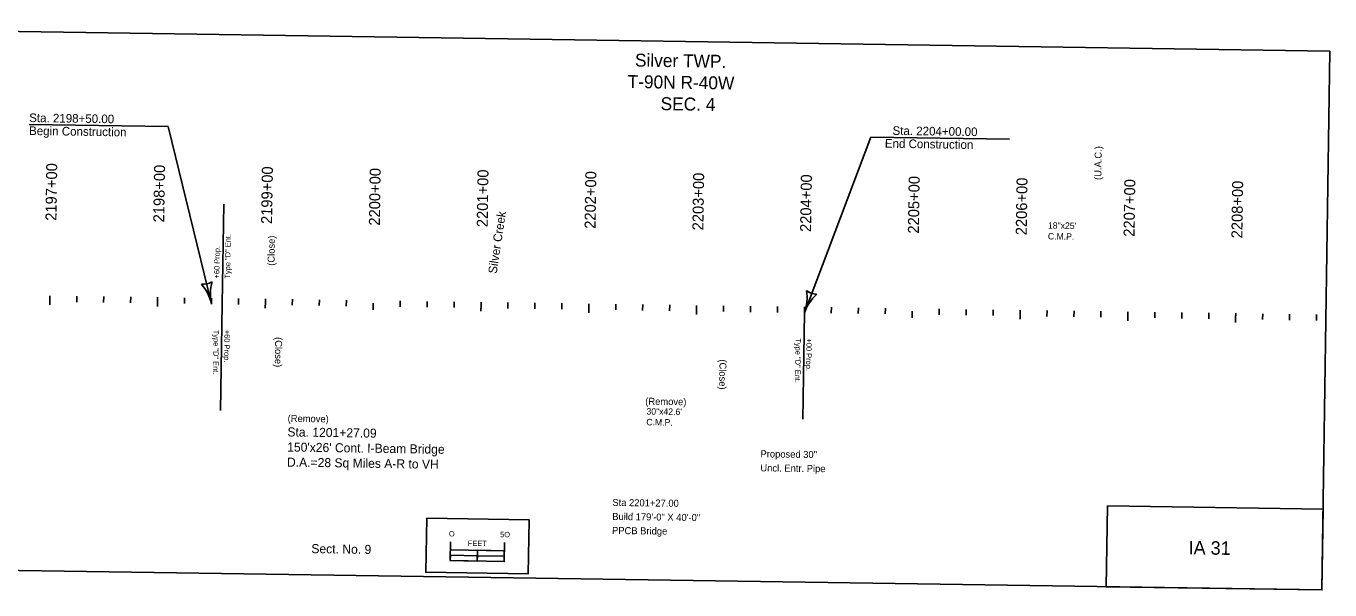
# Model space of a CAD drawing. Extents: x 14295116 to 14303545, y 8637313 to 8653417.
# Drawn here: x 14300189 to 14301398, y 8637313 to 8637836 of the extents above; entities that cross this region are included whole.
import ezdxf

# ---------------------------------------------------------------- set-up
doc = ezdxf.new("R2010")
doc.units = 0
for name, color, linetype in [('_CIVIL_CONSTRUCTION', 7, 'Continuous'), ('Draft_DNC', 7, 'Continuous'), ('dsnCellsNorthArrow', 7, 'Continuous'), ('dsnCellsScaleBlock', 7, 'Continuous'), ('dsnProfileBarGraphArrows', 7, 'Continuous'), ('dsnProfileDitchGradePropLeft', 7, 'Continuous'), ('dsnProfileGradeExistLine', 7, 'Continuous'), ('dsnTextFinalPlan', 7, 'Continuous'), ('dsnTextNote', 7, 'Continuous'), ('dsnTextProfileBarGraphRight', 7, 'Continuous'), ('dsnTextProfileDitchPropLeft', 7, 'Continuous'), ('G Prop 6 Valve (B1) CELL', 7, 'Continuous')]:
    doc.layers.add(name, color=color, linetype=linetype)

msp = doc.modelspace()

# ---------------------------------------------------------------- linework, layer by layer
at = {"layer": '_CIVIL_CONSTRUCTION'}
for p, q in [((14299830.8, 8637836.3), (14301398.1, 8637813)), ((14301390.7, 8637313), (14301398.1, 8637813)), ((14299823.4, 8637336.3), (14301390.7, 8637313))]:
    msp.add_line(p, q, dxfattribs=at)
at = {"layer": 'Draft_DNC'}
for p, q in [((14300210.9, 8637583.6), (14300210.8, 8637577.5)), ((14300235.8, 8637580.2), (14300235.9, 8637585.7)), ((14300260.8, 8637579.8), (14300260.9, 8637585.3)), ((14300285.8, 8637579.5), (14300285.9, 8637584.9)), ((14300310.8, 8637582.2), (14300310.8, 8637576)), ((14300335.8, 8637578.7), (14300335.9, 8637584.2)), ((14300360.8, 8637578.4), (14300360.9, 8637583.8)), ((14300385.8, 8637578), (14300385.9, 8637583.4)), ((14300410.8, 8637580.7), (14300410.7, 8637574.6)), ((14300435.8, 8637577.2), (14300435.9, 8637582.7)), ((14300460.8, 8637576.9), (14300460.9, 8637582.3)), ((14300485.8, 8637576.5), (14300485.9, 8637582)), ((14300510.8, 8637579.2), (14300510.7, 8637573.1)), ((14300535.8, 8637575.8), (14300535.9, 8637581.2)), ((14300560.8, 8637575.4), (14300560.9, 8637580.8)), ((14300585.8, 8637575), (14300585.8, 8637580.5)), ((14300610.8, 8637577.7), (14300610.7, 8637571.6)), ((14300635.8, 8637574.3), (14300635.8, 8637579.7)), ((14300660.8, 8637573.9), (14300660.8, 8637579.4)), ((14300685.8, 8637573.5), (14300685.8, 8637579)), ((14300710.8, 8637576.2), (14300710.7, 8637570.1)), ((14300735.8, 8637572.8), (14300735.8, 8637578.3)), ((14300760.7, 8637572.4), (14300760.8, 8637577.9)), ((14300785.7, 8637572), (14300785.8, 8637577.5)), ((14300810.8, 8637574.7), (14300810.7, 8637568.6)), ((14300835.7, 8637571.3), (14300835.8, 8637576.8)), ((14300860.7, 8637570.9), (14300860.8, 8637576.4)), ((14300885.7, 8637570.6), (14300885.8, 8637576)), ((14300935.7, 8637569.8), (14300935.8, 8637575.3)), ((14300960.7, 8637569.5), (14300960.8, 8637574.9)), ((14300985.7, 8637569.1), (14300985.8, 8637574.5)), ((14300910.8, 8637573.3), (14300910.7, 8637567.1)), ((14301010.8, 8637571.8), (14301010.7, 8637565.6)), ((14301035.7, 8637568.3), (14301035.8, 8637573.8)), ((14301060.7, 8637568), (14301060.8, 8637573.4)), ((14301085.7, 8637567.6), (14301085.8, 8637573.1)), ((14301110.8, 8637570.3), (14301110.7, 8637564.2)), ((14301135.7, 8637566.9), (14301135.8, 8637572.3)), ((14301160.7, 8637566.5), (14301160.8, 8637571.9)), ((14301185.7, 8637566.1), (14301185.8, 8637571.6)), ((14301210.7, 8637568.8), (14301210.7, 8637562.7)), ((14301235.7, 8637565.4), (14301235.8, 8637570.8)), ((14301260.7, 8637565), (14301260.8, 8637570.5)), ((14301285.7, 8637564.6), (14301285.8, 8637570.1)), ((14301310.7, 8637567.3), (14301310.6, 8637561.2)), ((14301335.7, 8637563.9), (14301335.8, 8637569.3)), ((14301360.7, 8637563.5), (14301360.8, 8637569)), ((14301385.7, 8637563.1), (14301385.8, 8637568.6))]:
    msp.add_line(p, q, dxfattribs=at)
at = {"layer": 'dsnCellsNorthArrow'}
for p, q in [((14300191.8, 8637744.9), (14300320.7, 8637743)), ((14300360.8, 8637578.4), (14300320.7, 8637743)), ((14300910.7, 8637570.2), (14300972.2, 8637733.3)), ((14301101.1, 8637731.4), (14300972.2, 8637733.3))]:
    msp.add_line(p, q, dxfattribs=at)
for centre, radius, start, end in [((14300353, 8637613.1), 16.4, 264.823, 300.2897), ((14300402.3, 8637587.6), 42.5, 164.4839, 192.5564), ((14300319.3, 8637569.1), 42.5, 12.5564, 40.6289), ((14300870.7, 8637584.4), 42.5, 340.4638, 8.5362), ((14300950.8, 8637556), 42.5, 132.3913, 160.4638), ((14300922.6, 8637603.8), 16.4, 232.7304, 268.1971)]:
    msp.add_arc(centre, radius, start, end, dxfattribs=at)
at = {"layer": 'dsnCellsScaleBlock'}
msp.add_line((14300607.3, 8637339.8), (14300607.4, 8637349.8), dxfattribs=at)
msp.add_line((14300607.3, 8637339.8), (14300607.4, 8637349.8), dxfattribs=at)
for points in [[(14300559.6, 8637329.5), (14300560.4, 8637379.5), (14300655.4, 8637378.1), (14300654.6, 8637328.1)], [(14300582.3, 8637340.2), (14300607.3, 8637339.8), (14300607.4, 8637344.8), (14300582.4, 8637345.2)], [(14300607.4, 8637344.8), (14300632.4, 8637344.5), (14300632.4, 8637349.4), (14300607.4, 8637349.8)]]:
    msp.add_lwpolyline(points, close=True, dxfattribs=at)
for points in [[(14300582.5, 8637357.7), (14300582.3, 8637340.2), (14300632.3, 8637339.4), (14300632.5, 8637356.9)], [(14300582.4, 8637350.2), (14300632.4, 8637349.4)]]:
    msp.add_lwpolyline(points, dxfattribs=at)
at = {"layer": 'dsnProfileDitchGradePropLeft'}
for p, q in [((14300370.8, 8637578.2), (14300372.2, 8637670.9)), ((14300370.8, 8637578.2), (14300369.3, 8637479.6)), ((14300910.7, 8637570.2), (14300909.3, 8637471.6))]:
    msp.add_line(p, q, dxfattribs=at)
at = {"layer": 'dsnTextFinalPlan'}
msp.add_lwpolyline([(14300560.4, 8637379.5), (14300655.4, 8637378.1), (14300654.6, 8637328.1), (14300559.6, 8637329.5)], close=True, dxfattribs=at)
msp.add_lwpolyline([(14300560.4, 8637379.5), (14300655.4, 8637378.1), (14300654.6, 8637328.1), (14300559.6, 8637329.5)], close=True, dxfattribs=at)
at = {"layer": 'dsnTextProfileDitchPropLeft'}
for points in [[(14301191.9, 8637391), (14301391.8, 8637388), (14301390.7, 8637313), (14301190.7, 8637316)], [(14301390.7, 8637313), (14301190.7, 8637316), (14301191.9, 8637391), (14301391.8, 8637388)]]:
    msp.add_lwpolyline(points, close=True, dxfattribs=at)
at = {"layer": 'G Prop 6 Valve (B1) CELL'}
for p, q in [((14300210.8, 8637580.6), (14300210.9, 8637586)), ((14300310.8, 8637579.1), (14300310.9, 8637584.6)), ((14300410.8, 8637577.6), (14300410.9, 8637583.1)), ((14300510.8, 8637579.2), (14300510.7, 8637573.1)), ((14300610.8, 8637574.6), (14300610.8, 8637580.1)), ((14300710.8, 8637573.2), (14300710.8, 8637578.6)), ((14300810.7, 8637571.7), (14300810.8, 8637577.1)), ((14300910.7, 8637570.2), (14300910.8, 8637575.7)), ((14301010.8, 8637571.8), (14301010.7, 8637565.6)), ((14301110.7, 8637567.2), (14301110.8, 8637572.7)), ((14301210.7, 8637565.7), (14301210.8, 8637571.2)), ((14301310.7, 8637564.3), (14301310.8, 8637569.7))]:
    msp.add_line(p, q, dxfattribs=at)

# ---------------------------------------------------------------- texts
at = {"layer": 'Draft_DNC'}
for s, p in [('2197+00', (14300217, 8637655.5)), ('2198+00', (14300317, 8637654)), ('2199+00', (14300417, 8637652.5)), ('2200+00', (14300517, 8637651)), ('2201+00', (14300617, 8637649.6)), ('2202+00', (14300717, 8637648.1)), ('2203+00', (14300817, 8637646.6)), ('2204+00', (14300916.9, 8637645.1)), ('2205+00', (14301016.9, 8637643.6)), ('2206+00', (14301116.9, 8637642.1)), ('2207+00', (14301216.9, 8637640.7)), ('2208+00', (14301316.9, 8637639.2))]:
    msp.add_text(s, height=10.2, rotation=89.1493, dxfattribs=at).set_placement(p)
at = {"layer": 'dsnCellsNorthArrow'}
for s, p in [('Sta. 2198+50.00', (14300191.7, 8637747.2)), ('Begin Construction', (14300191.6, 8637735.2)), ('End Construction', (14300985.3, 8637723.4)), ('Sta. 2204+00.00', (14300992.4, 8637735.3))]:
    msp.add_text(s, height=8, rotation=359.1493, dxfattribs=at).set_placement(p)
at = {"layer": 'dsnCellsScaleBlock'}
for s, p in [('O', (14300581, 8637362.7)), ('FEET', (14300598.5, 8637353.9)), ('5O', (14300628.5, 8637362))]:
    msp.add_text(s, height=5, rotation=359.1493, dxfattribs=at).set_placement(p)
at = {"layer": 'dsnProfileBarGraphArrows'}
for s, rotation, p in [('(U.A.C.)', 89.2807, (14301186.1, 8637693.4)), ('(Close)', 89.2287, (14300419.3, 8637613.8)), ('(Close)', 269.2287, (14300419.9, 8637547.7)), ('(Close)', 269.2287, (14300832, 8637527)), ('(Remove)', 359.2287, (14300763.1, 8637484.9))]:
    msp.add_text(s, height=6.5, rotation=rotation, dxfattribs=at).set_placement(p)
at = {"layer": 'dsnProfileDitchGradePropLeft'}
for s, rotation, p in [('Type "D" Ent.', 89.1628, (14300378.1, 8637601.9)), ('+60 Prop.', 89.1628, (14300368.1, 8637602)), ('Type "D" Ent.', 269.1628, (14300362.9, 8637554.5)), ('+60 Prop.', 269.1628, (14300372.9, 8637554.4)), ('Type "D" Ent.', 269.1628, (14300902.6, 8637546.5)), ('+00 Prop.', 269.1628, (14300912.6, 8637546.4))]:
    msp.add_text(s, height=5, rotation=rotation, dxfattribs=at).set_placement(p)
at = {"layer": 'dsnProfileGradeExistLine'}
for s, height, p in [('Silver TWP.', 12, (14300753.5, 8637798.7)), ('T-90N R-40W', 12, (14300746.7, 8637778.8)), ('SEC. 4', 12, (14300777.3, 8637758.3)), ('18"x25\'', 6, (14301136.6, 8637648.3)), ('C.M.P.', 6, (14301136.5, 8637638.3)), ('30"x42.6\'', 6, (14300764.2, 8637475.8)), ('C.M.P.', 6, (14300764.1, 8637465.8)), ('Sta. 1201+27.09', 8.4, (14300431.2, 8637455.5)), ("150'x26' Cont. I-Beam Bridge ", 8.4, (14300431, 8637441.5)), ('D.A.=28 Sq Miles A-R to VH', 8.4, (14300430.8, 8637427.5)), ('Sect. No. 9', 8.4, (14300453.4, 8637347.2))]:
    msp.add_text(s, height=height, rotation=359.1493, dxfattribs=at).set_placement(p)
at = {"layer": 'dsnTextNote'}
msp.add_text('Silver Creek', height=8, rotation=81.4251, dxfattribs=at).set_placement((14300625.3, 8637606.1))
at = {"layer": 'dsnTextProfileBarGraphRight'}
for s, p in [('(Remove)', (14300431.4, 8637469)), ('Proposed 30"', (14300870, 8637436.1)), ('Uncl. Entr. Pipe', (14300869.9, 8637423.1)), ('Sta 2201+27.00', (14300732.6, 8637391)), ('Build 179\'-0" X 40\'-0"', (14300732.5, 8637378)), ('PPCB Bridge', (14300732.3, 8637365))]:
    msp.add_text(s, height=6.5, rotation=359.2287, dxfattribs=at).set_placement(p)
at = {"layer": 'dsnTextProfileDitchPropLeft'}
msp.add_text('IA 31', height=12.5, rotation=359.1493, dxfattribs=at).set_placement((14301267, 8637346.1))
at = {"layer": 'G Prop 6 Valve (B1) CELL'}
for s, p in [('2200+00', (14300517, 8637651)), ('2205+00', (14301016.9, 8637643.6))]:
    msp.add_text(s, height=10.2, rotation=89.1493, dxfattribs=at).set_placement(p)

doc.saveas('drawing.dxf')
